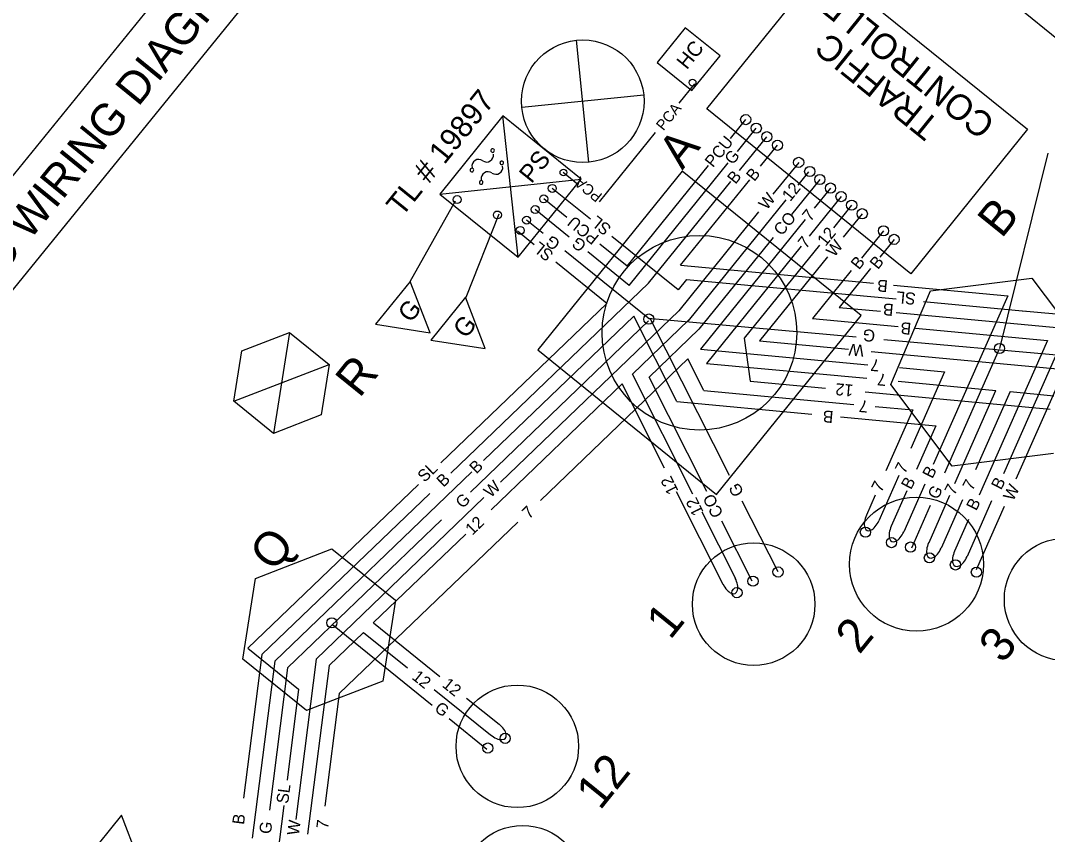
# Model space of a CAD drawing. Extents: x 592613 to 600223, y 4837996 to 4840103.
# Drawn here: x 592734.31 to 592762.96, y 4838919.81 to 4838942.52 of the extents above; entities that cross this region are included whole.
import ezdxf

# ---------------------------------------------------------------- set-up
doc = ezdxf.new("R2010")
doc.units = 0
for name, color, linetype in [('ENG_BORDER', 7, 'Continuous'), ('ENG_TITLEBLOCK', 7, 'Continuous'), ('Level 43', 7, 'Continuous'), ('Level 57', 7, 'Continuous'), ('TCS_CONTROLLER', 7, 'Continuous'), ('TCS_ELEC-CHAMBER-NEW', 7, 'Continuous'), ('TCS_FUSE', 7, 'Continuous'), ('TCS_HYDROSUPPLY', 7, 'Continuous'), ('TCS_PLATE', 7, 'Continuous'), ('TCS_POLE-EXIST', 7, 'Continuous'), ('TCS_POLE-NEW', 7, 'Continuous'), ('TCS_POWER', 7, 'Continuous'), ('TCS_WR_12', 7, 'Continuous'), ('TCS_WR_7', 7, 'Continuous'), ('TCS_WR_B', 7, 'Continuous'), ('TCS_WR_CO', 7, 'Continuous'), ('TCS_WR_G', 7, 'Continuous'), ('TCS_WR_PCA', 7, 'Continuous'), ('TCS_WR_PCU', 7, 'Continuous'), ('TCS_WR_SL', 7, 'Continuous'), ('TCS_WR_W', 7, 'Continuous')]:
    doc.layers.add(name, color=color, linetype=linetype)

msp = doc.modelspace()

# ---------------------------------------------------------------- linework, layer by layer
at = {"layer": 'ENG_BORDER'}
msp.add_line((592790.401, 4838919.927), (592686.018, 4839004.737), dxfattribs=at)
at = {"layer": 'ENG_TITLEBLOCK'}
for p, q in [((592720.007, 4838920.852), (592747.546, 4838954.746)), ((592721.564, 4838919.587), (592749.103, 4838953.481))]:
    msp.add_line(p, q, dxfattribs=at)
at = {"layer": 'Level 57'}
for centre in [(592753.056, 4838940.788), (592749.454, 4838938.28)]:
    msp.add_circle(centre, 0.095, dxfattribs=at)
at = {"layer": 'TCS_CONTROLLER'}
msp.add_lwpolyline([(592756.709, 4838944.087), (592762.404, 4838939.488), (592759.147, 4838935.456), (592753.453, 4838940.055)], close=True, dxfattribs=at)
at = {"layer": 'TCS_ELEC-CHAMBER-NEW'}
for p, q in [((592752.769, 4838938.317), (592748.741, 4838933.329)), ((592757.758, 4838934.288), (592752.769, 4838938.317)), ((592759.698, 4838934.983), (592762.523, 4838935.33)), ((592762.523, 4838935.33), (592764.236, 4838933.056)), ((592758.586, 4838932.363), (592759.698, 4838934.983)), ((592753.729, 4838929.3), (592757.758, 4838934.288)), ((592740.48, 4838933.304), (592741.81, 4838933.817)), ((592741.81, 4838933.817), (592741.368, 4838931.001)), ((592741.81, 4838933.817), (592742.918, 4838932.921)), ((592740.259, 4838931.897), (592740.48, 4838933.304)), ((592748.741, 4838933.329), (592753.729, 4838929.3)), ((592740.259, 4838931.897), (592742.918, 4838932.921)), ((592742.918, 4838932.921), (592742.697, 4838931.514)), ((592760.299, 4838930.09), (592758.586, 4838932.363)), ((592741.368, 4838931.001), (592740.259, 4838931.897)), ((592742.697, 4838931.514), (592741.368, 4838931.001)), ((592763.124, 4838930.437), (592760.299, 4838930.09)), ((592740.866, 4838926.956), (592742.994, 4838927.776)), ((592742.994, 4838927.776), (592744.768, 4838926.343)), ((592740.513, 4838924.704), (592740.866, 4838926.956)), ((592744.768, 4838926.343), (592744.414, 4838924.091)), ((592742.287, 4838923.271), (592740.513, 4838924.704)), ((592744.414, 4838924.091), (592742.287, 4838923.271))]:
    msp.add_line(p, q, dxfattribs=at)
msp.add_circle((592753.249, 4838933.81), 2.715, dxfattribs=at)
at = {"layer": 'TCS_FUSE'}
for centre, radius, start, end in [((592747.313, 4838938.762), 0.189, 233.7917, 10.4404), ((592747.476, 4838938.894), 0.0513, 51.0744, 231.0744), ((592747.476, 4838938.894), 0.0513, 231.0744, 51.0744), ((592746.9, 4838938.347), 0.0513, 51.0744, 231.0744), ((592747.091, 4838938.458), 0.189, 53.7917, 190.4404), ((592747.572, 4838938.419), 0.189, 233.7917, 10.4404), ((592747.735, 4838938.551), 0.0513, 51.0744, 231.0744), ((592747.735, 4838938.551), 0.0513, 231.0744, 51.0744), ((592746.9, 4838938.347), 0.0513, 231.0744, 51.0744), ((592747.349, 4838938.115), 0.189, 53.7917, 190.4404), ((592747.159, 4838938.005), 0.0513, 51.0744, 231.0744), ((592747.159, 4838938.005), 0.0513, 231.0744, 51.0744)]:
    msp.add_arc(centre, radius, start, end, dxfattribs=at)
at = {"layer": 'TCS_HYDROSUPPLY'}
for p, q in [((592752.855, 4838942.322), (592752.073, 4838941.354)), ((592753.823, 4838941.54), (592752.855, 4838942.322)), ((592752.073, 4838941.354), (592753.041, 4838940.572)), ((592753.041, 4838940.572), (592753.823, 4838941.54))]:
    msp.add_line(p, q, dxfattribs=at)
at = {"layer": 'TCS_PLATE'}
for p, q in [((592745.18, 4838935.241), (592744.213, 4838934.044)), ((592745.733, 4838933.805), (592745.18, 4838935.241)), ((592746.72, 4838934.801), (592745.753, 4838933.604)), ((592747.274, 4838933.365), (592746.72, 4838934.801)), ((592744.213, 4838934.044), (592745.733, 4838933.805)), ((592745.753, 4838933.604), (592747.274, 4838933.365)), ((592737.122, 4838920.344), (592736.155, 4838919.147)), ((592737.675, 4838918.908), (592737.122, 4838920.344))]:
    msp.add_line(p, q, dxfattribs=at)
at = {"layer": 'TCS_POLE-EXIST'}
for p, q in [((592750.166, 4838938.568), (592749.821, 4838941.97)), ((592751.694, 4838940.441), (592748.292, 4838940.096))]:
    msp.add_line(p, q, dxfattribs=at)
msp.add_circle((592749.993, 4838940.269), 1.71, dxfattribs=at)
at = {"layer": 'TCS_POLE-NEW'}
for centre, radius in [((592759.303, 4838927.35), 1.869), ((592763.465, 4838926.369), 1.71), ((592754.762, 4838926.235), 1.71), ((592748.168, 4838922.268), 1.71), ((592748.317, 4838918.349), 1.71)]:
    msp.add_circle(centre, radius, dxfattribs=at)
at = {"layer": 'TCS_POWER'}
for p, q in [((592747.768, 4838939.861), (592746.005, 4838937.679)), ((592748.187, 4838935.916), (592747.768, 4838939.861)), ((592749.95, 4838938.098), (592747.768, 4838939.861)), ((592746.005, 4838937.679), (592749.95, 4838938.098)), ((592748.187, 4838935.916), (592749.95, 4838938.098)), ((592746.005, 4838937.679), (592748.187, 4838935.916))]:
    msp.add_line(p, q, dxfattribs=at)
at = {"layer": 'TCS_WR_12'}
for p, q in [((592756.291, 4838938.297), (592755.995, 4838937.93)), ((592755.661, 4838937.516), (592752.936, 4838934.144)), ((592757.495, 4838937.369), (592756.985, 4838936.737)), ((592756.596, 4838936.255), (592754.497, 4838933.656)), ((592752.944, 4838934.161), (592751.377, 4838932.655)), ((592754.497, 4838933.656), (592754.661, 4838932.459)), ((592751.091, 4838932.38), (592747.44, 4838928.872)), ((592752.276, 4838930.03), (592751.091, 4838932.38)), ((592753.066, 4838929.308), (592751.377, 4838932.655)), ((592754.661, 4838932.459), (592756.763, 4838932.264)), ((592757.868, 4838932.161), (592762.734, 4838931.707)), ((592762.734, 4838931.707), (592763.036, 4838931.679)), ((592753.912, 4838926.787), (592752.611, 4838929.366)), ((592754.252, 4838926.958), (592753.322, 4838928.8)), ((592746.728, 4838928.188), (592744.151, 4838925.711)), ((592744.154, 4838925.714), (592746.01, 4838924.214)), ((592743.877, 4838925.448), (592742.919, 4838924.528)), ((592743.877, 4838925.448), (592745.103, 4838924.459)), ((592742.918, 4838924.521), (592742.319, 4838919.815)), ((592745.851, 4838923.854), (592747.422, 4838922.586)), ((592746.752, 4838923.615), (592747.661, 4838922.882))]:
    msp.add_line(p, q, dxfattribs=at)
for centre, major_axis in [((592754.078, 4838926.876), (-0.171, 0.339)), ((592747.542, 4838922.735), (-0.296, 0.239))]:
    msp.add_ellipse(centre, major_axis=major_axis, ratio=0.5, start_param=1.570796, end_param=4.712389, dxfattribs=at)
at = {"layer": 'TCS_WR_7'}
for p, q in [((592756.904, 4838937.846), (592756.449, 4838937.283)), ((592757.2, 4838937.608), (592756.307, 4838936.502)), ((592756.194, 4838936.967), (592753.274, 4838933.352)), ((592756.083, 4838936.225), (592753.442, 4838932.955)), ((592753.274, 4838933.352), (592757.95, 4838932.916)), ((592752.925, 4838933.083), (592748.812, 4838929.131)), ((592753.371, 4838932.198), (592752.925, 4838933.083)), ((592753.442, 4838932.955), (592757.914, 4838932.538)), ((592758.826, 4838932.835), (592760.083, 4838932.718)), ((592760.083, 4838932.718), (592759.142, 4838930.581)), ((592758.791, 4838932.456), (592761.517, 4838932.202)), ((592753.371, 4838932.198), (592757.558, 4838931.808)), ((592761.512, 4838932.19), (592760.367, 4838929.593)), ((592761.916, 4838932.165), (592760.954, 4838929.981)), ((592761.916, 4838932.165), (592763.133, 4838932.052)), ((592758.149, 4838931.753), (592759.2, 4838931.655)), ((592759.2, 4838931.655), (592758.449, 4838929.952)), ((592758.81, 4838929.828), (592758.253, 4838928.563)), ((592758.151, 4838929.276), (592757.905, 4838928.716)), ((592760.225, 4838929.269), (592759.644, 4838927.95)), ((592760.586, 4838929.147), (592759.991, 4838927.796)), ((592748.178, 4838928.521), (592743.202, 4838923.739)), ((592743.202, 4838923.739), (592742.802, 4838920.598))]:
    msp.add_line(p, q, dxfattribs=at)
for centre in [(592758.079, 4838928.64), (592759.816, 4838927.873)]:
    msp.add_ellipse(centre, major_axis=(0.153, 0.348), ratio=0.5, start_param=1.570796, end_param=4.712389, dxfattribs=at)
at = {"layer": 'TCS_WR_B'}
for p, q in [((592754.369, 4838938.336), (592755.13, 4838939.279)), ((592754.953, 4838938.455), (592755.426, 4838939.04)), ((592751.831, 4838935.193), (592754.121, 4838938.029)), ((592752.723, 4838935.693), (592754.651, 4838938.08)), ((592758.382, 4838936.652), (592757.769, 4838935.893)), ((592758.678, 4838936.414), (592758.278, 4838935.919)), ((592752.723, 4838935.693), (592758.108, 4838935.191)), ((592757.485, 4838935.542), (592756.406, 4838934.205)), ((592758.02, 4838935.599), (592757.147, 4838934.518)), ((592751.831, 4838935.193), (592746.312, 4838929.89)), ((592758.666, 4838935.14), (592761.85, 4838934.843)), ((592761.85, 4838934.843), (592759.772, 4838930.129)), ((592757.147, 4838934.518), (592758.298, 4838934.411)), ((592751.414, 4838934.269), (592747.225, 4838930.241)), ((592752.616, 4838931.886), (592751.414, 4838934.269)), ((592756.406, 4838934.205), (592758.794, 4838933.983)), ((592758.733, 4838934.37), (592761.528, 4838934.11)), ((592761.528, 4838934.11), (592763.619, 4838933.915)), ((592759.274, 4838933.938), (592762.957, 4838933.595)), ((592762.957, 4838933.595), (592761.055, 4838929.278)), ((592763.356, 4838933.558), (592761.732, 4838929.873)), ((592752.616, 4838931.886), (592756.384, 4838931.536)), ((592757.187, 4838931.461), (592759.839, 4838931.214)), ((592759.839, 4838931.214), (592759.3, 4838929.993)), ((592746.896, 4838929.924), (592741.402, 4838924.645)), ((592759.533, 4838929.587), (592758.947, 4838928.256)), ((592745.723, 4838929.324), (592741.042, 4838924.826)), ((592759.038, 4838929.401), (592758.6, 4838928.41)), ((592761.399, 4838929.116), (592760.714, 4838927.563)), ((592760.754, 4838928.595), (592760.366, 4838927.717)), ((592741.042, 4838924.826), (592740.532, 4838920.822)), ((592741.402, 4838924.645), (592740.773, 4838919.704))]:
    msp.add_line(p, q, dxfattribs=at)
for centre in [(592758.773, 4838928.333), (592760.54, 4838927.64)]:
    msp.add_ellipse(centre, major_axis=(0.153, 0.348), ratio=0.5, start_param=1.570796, end_param=4.712389, dxfattribs=at)
at = {"layer": 'TCS_WR_CO'}
for p, q in [((592756.608, 4838938.085), (592755.819, 4838937.108)), ((592755.305, 4838936.471), (592753.232, 4838933.905)), ((592753.232, 4838933.905), (592751.845, 4838932.572)), ((592753.457, 4838929.376), (592751.845, 4838932.572)), ((592754.719, 4838926.876), (592753.873, 4838928.552))]:
    msp.add_line(p, q, dxfattribs=at)
at = {"layer": 'TCS_WR_G'}
for p, q in [((592754.313, 4838938.871), (592754.835, 4838939.518)), ((592762.964, 4838938.82), (592761.62, 4838933.368)), ((592751.29, 4838935.128), (592754.053, 4838938.549)), ((592745.18, 4838935.241), (592746.447, 4838937.489)), ((592749.616, 4838936.48), (592748.667, 4838937.247)), ((592747.65, 4838937.121), (592746.727, 4838934.796)), ((592748.891, 4838936.577), (592748.428, 4838936.951)), ((592751.852, 4838934.186), (592749.489, 4838936.094)), ((592751.29, 4838935.128), (592750.132, 4838936.063)), ((592751.827, 4838934.139), (592746.861, 4838929.363)), ((592751.818, 4838934.213), (592757.621, 4838933.691)), ((592754.083, 4838929.822), (592751.871, 4838934.208)), ((592758.397, 4838933.622), (592763.425, 4838933.17)), ((592761.601, 4838933.334), (592760.083, 4838929.89)), ((592755.441, 4838927.133), (592754.445, 4838929.105)), ((592759.685, 4838928.986), (592759.162, 4838927.8)), ((592746.051, 4838928.584), (592741.761, 4838924.459)), ((592743.016, 4838925.665), (592745.797, 4838923.419)), ((592741.761, 4838924.459), (592741.256, 4838920.491)), ((592746.266, 4838923.047), (592747.315, 4838922.193))]:
    msp.add_line(p, q, dxfattribs=at)
at = {"layer": 'TCS_WR_PCA'}
for p, q in [((592752.686, 4838940.211), (592753.124, 4838940.754)), ((592750.463, 4838937.461), (592752.024, 4838939.393)), ((592749.86, 4838937.948), (592749.446, 4838938.283))]:
    msp.add_line(p, q, dxfattribs=at)
at = {"layer": 'TCS_WR_PCU'}
for p, q in [((592754.116, 4838939.233), (592754.539, 4838939.756)), ((592751.233, 4838935.663), (592753.502, 4838938.472)), ((592749.546, 4838937.025), (592748.905, 4838937.542)), ((592751.233, 4838935.663), (592750.469, 4838936.28))]:
    msp.add_line(p, q, dxfattribs=at)
at = {"layer": 'TCS_WR_SL'}
for p, q in [((592750.206, 4838936.98), (592749.144, 4838937.838)), ((592748.639, 4838936.266), (592748.176, 4838936.64)), ((592752.654, 4838935.003), (592750.802, 4838936.499)), ((592750.666, 4838934.629), (592749.238, 4838935.782)), ((592752.892, 4838935.297), (592752.654, 4838935.003)), ((592752.892, 4838935.296), (592758.735, 4838934.751)), ((592759.503, 4838934.68), (592762.357, 4838934.414)), ((592750.666, 4838934.629), (592746.035, 4838930.179)), ((592762.268, 4838934.422), (592763.834, 4838934.276)), ((592745.409, 4838929.577), (592740.651, 4838925.005)), ((592740.651, 4838925.005), (592742.068, 4838923.86)), ((592742.068, 4838923.86), (592741.745, 4838921.32)), ((592741.655, 4838920.617), (592741.275, 4838917.629))]:
    msp.add_line(p, q, dxfattribs=at)
at = {"layer": 'TCS_WR_W'}
for p, q in [((592756.017, 4838938.563), (592755.298, 4838937.672)), ((592754.901, 4838937.18), (592752.673, 4838934.421)), ((592757.791, 4838937.13), (592757.263, 4838936.477)), ((592756.82, 4838935.927), (592754.924, 4838933.58)), ((592752.673, 4838934.421), (592747.697, 4838929.64)), ((592754.924, 4838933.58), (592757.404, 4838933.349)), ((592758.038, 4838933.29), (592763.432, 4838932.787)), ((592763.432, 4838932.787), (592762.08, 4838929.72)), ((592747.23, 4838929.214), (592742.558, 4838924.702)), ((592761.746, 4838928.963), (592760.967, 4838927.194)), ((592742.558, 4838924.702), (592741.987, 4838920.222))]:
    msp.add_line(p, q, dxfattribs=at)
for centre, radius in [((592754.539, 4838939.756), 0.142), ((592754.835, 4838939.518), 0.142), ((592755.13, 4838939.279), 0.142), ((592755.426, 4838939.04), 0.142), ((592756.017, 4838938.563), 0.142), ((592756.326, 4838938.31), 0.142), ((592756.608, 4838938.085), 0.142), ((592749.144, 4838937.838), 0.111), ((592756.904, 4838937.846), 0.142), ((592746.49, 4838937.526), 0.111), ((592748.905, 4838937.542), 0.111), ((592757.2, 4838937.608), 0.142), ((592748.667, 4838937.247), 0.111), ((592757.495, 4838937.369), 0.142), ((592757.791, 4838937.13), 0.142), ((592747.612, 4838937.095), 0.111), ((592748.428, 4838936.951), 0.111), ((592748.25, 4838936.663), 0.111), ((592758.382, 4838936.652), 0.142), ((592758.678, 4838936.414), 0.142), ((592751.835, 4838934.192), 0.142), ((592761.62, 4838933.368), 0.142), ((592757.879, 4838928.246), 0.142), ((592758.607, 4838927.952), 0.142), ((592759.137, 4838927.828), 0.142), ((592759.663, 4838927.526), 0.142), ((592755.441, 4838927.133), 0.142), ((592760.39, 4838927.33), 0.142), ((592760.975, 4838927.127), 0.142), ((592754.743, 4838926.877), 0.142), ((592754.296, 4838926.556), 0.142), ((592742.994, 4838925.714), 0.142), ((592747.346, 4838922.22), 0.142), ((592747.829, 4838922.491), 0.142)]:
    msp.add_circle(centre, radius, dxfattribs=at)

# ---------------------------------------------------------------- texts
at = {"layer": 'Level 43'}
msp.add_text('SCHEMATIC WIRING DIAGRAM', height=0.9, rotation=50.9062, dxfattribs=at).set_placement((592729.874, 4838930.598))
at = {"layer": 'TCS_CONTROLLER'}
for s, p in [('CONTROLLER', (592761.543, 4838939.719)), ('TRAFFIC', (592759.99, 4838939.691))]:
    msp.add_text(s, height=0.7125, rotation=141.0744, dxfattribs=at).set_placement(p)
at = {"layer": 'TCS_ELEC-CHAMBER-NEW'}
for s, p in [('A', (592752.77, 4838938.33)), ('B', (592761.677, 4838936.417)), ('R', (592743.763, 4838931.964)), ('Q', (592741.372, 4838927.107))]:
    msp.add_text(s, height=0.95, rotation=51.0744, dxfattribs=at).set_placement(p)
at = {"layer": 'TCS_HYDROSUPPLY'}
msp.add_text('HC', height=0.4116, rotation=51.0575, dxfattribs=at).set_placement((592752.897, 4838941.131))
at = {"layer": 'TCS_PLATE'}
for p in [(592745.192, 4838934.062), (592746.732, 4838933.622)]:
    msp.add_text('G', height=0.513, rotation=51.0744, dxfattribs=at).set_placement(p)
at = {"layer": 'TCS_POLE-NEW'}
for s, p in [('1', (592752.432, 4838925.217)), ('2', (592757.711, 4838924.81)), ('3', (592761.711, 4838924.55)), ('12', (592750.475, 4838920.459))]:
    msp.add_text(s, height=0.95, rotation=51.0744, dxfattribs=at).set_placement(p)
at = {"layer": 'TCS_POWER'}
for s, height, rotation, p in [('TL # 19897', 0.6175, 51.0744, (592744.948, 4838937.016)), ('PS', 0.4986, 51.0091, (592748.563, 4838937.951))]:
    msp.add_text(s, height=height, rotation=rotation, dxfattribs=at).set_placement(p)
at = {"layer": 'TCS_WR_12'}
for rotation, p in [(51.0744, (592755.781, 4838937.452)), (51.0744, (592756.766, 4838936.201)), (174.6781, (592757.553, 4838932.357)), (116.468, (592752.67, 4838929.398)), (116.468, (592753.374, 4838928.804)), (43.8597, (592746.911, 4838928.141)), (321.0744, (592745.204, 4838924.165)), (321.0744, (592746.048, 4838923.948))]:
    msp.add_text('12', height=0.3325, rotation=rotation, dxfattribs=at).set_placement(p)
at = {"layer": 'TCS_WR_7'}
for height, rotation, p in [(0.332, 51.0744, (592756.346, 4838936.89)), (0.333, 51.0744, (592756.223, 4838936.134)), (0.333, 174.6781, (592758.286, 4838933.056)), (0.333, 174.6781, (592758.475, 4838932.653)), (0.333, 174.6781, (592757.965, 4838931.909)), (0.332, 62.6356, (592758.979, 4838929.856)), (0.332, 62.6356, (592758.321, 4838929.337)), (0.332, 62.6356, (592760.361, 4838929.254)), (0.332, 62.6356, (592760.865, 4838929.381)), (0.333, 43.8597, (592748.495, 4838928.595)), (0.332, 82.7426, (592742.886, 4838919.951))]:
    msp.add_text('7', height=height, rotation=rotation, dxfattribs=at).set_placement(p)
at = {"layer": 'TCS_WR_B'}
for height, rotation, p in [(0.333, 51.0744, (592754.78, 4838938.011)), (0.333, 51.0744, (592754.254, 4838937.935)), (0.333, 51.0744, (592757.7, 4838935.548)), (0.333, 51.0744, (592758.228, 4838935.556)), (0.332, 174.6781, (592758.517, 4838935.269)), (0.332, 174.6781, (592758.677, 4838934.606)), (0.332, 174.6781, (592759.169, 4838934.081)), (0.332, 174.6781, (592756.999, 4838931.619)), (0.333, 43.8597, (592747.024, 4838929.853)), (0.332, 62.6356, (592759.745, 4838929.718)), (0.333, 43.8597, (592746.106, 4838929.481)), (0.332, 62.6356, (592759.151, 4838929.412)), (0.332, 62.6356, (592761.663, 4838929.404)), (0.332, 62.6356, (592760.968, 4838928.822)), (0.332, 82.7426, (592740.541, 4838920.07))]:
    msp.add_text('B', height=height, rotation=rotation, dxfattribs=at).set_placement(p)
at = {"layer": 'TCS_WR_CO'}
for rotation, p in [(51.0744, (592755.547, 4838936.495)), (116.468, (592753.924, 4838928.751))]:
    msp.add_text('CO', height=0.3325, rotation=rotation, dxfattribs=at).set_placement(p)
at = {"layer": 'TCS_WR_G'}
for height, rotation, p in [(0.333, 51.0744, (592754.177, 4838938.477)), (0.333, 141.0744, (592749.394, 4838936.338)), (0.333, 141.0744, (592750.124, 4838936.294)), (0.332, 174.6781, (592758.164, 4838933.881)), (0.333, 116.468, (592754.497, 4838929.341)), (0.332, 62.6356, (592759.892, 4838929.133)), (0.332, 43.8597, (592746.638, 4838928.887)), (0.333, 321.0744, (592745.831, 4838923.284)), (0.332, 82.7426, (592741.292, 4838919.808))]:
    msp.add_text('G', height=height, rotation=rotation, dxfattribs=at).set_placement(p)
at = {"layer": 'TCS_WR_PCA'}
for rotation, p in [(51.0574, (592752.245, 4838939.427)), (141.0574, (592750.562, 4838937.663))]:
    msp.add_text('PCA', height=0.2993, rotation=rotation, dxfattribs=at).set_placement(p)
at = {"layer": 'TCS_WR_PCU'}
for rotation, p in [(51.0744, (592753.626, 4838938.4)), (141.0744, (592750.473, 4838936.5))]:
    msp.add_text('PCU', height=0.3325, rotation=rotation, dxfattribs=at).set_placement(p)
at = {"layer": 'TCS_WR_SL'}
for rotation, p in [(141.0744, (592750.816, 4838936.756)), (141.0744, (592749.204, 4838936.032)), (174.6781, (592759.296, 4838934.918)), (43.8597, (592745.579, 4838929.618)), (82.7426, (592741.774, 4838920.654))]:
    msp.add_text('SL', height=0.3325, rotation=rotation, dxfattribs=at).set_placement(p)
at = {"layer": 'TCS_WR_W'}
for height, rotation, p in [(0.333, 51.0744, (592755.127, 4838937.214)), (0.333, 51.0744, (592757.012, 4838935.9)), (0.333, 174.6781, (592757.851, 4838933.469)), (0.333, 43.8597, (592747.425, 4838929.187)), (0.332, 62.6356, (592761.999, 4838929.092)), (0.332, 82.7426, (592742.072, 4838919.771))]:
    msp.add_text('W', height=height, rotation=rotation, dxfattribs=at).set_placement(p)

doc.saveas('drawing.dxf')
